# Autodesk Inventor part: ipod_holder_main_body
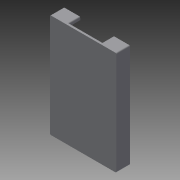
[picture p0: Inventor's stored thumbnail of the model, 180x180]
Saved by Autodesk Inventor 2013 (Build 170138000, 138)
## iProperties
Created: 2013-05
Part Number: ipod_holder_main_body
Material: Generic
Document SubType Name: Modeling
Designer: claudiu
Density: 1 g/cm^3
Author: claudiu
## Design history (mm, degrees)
sketch "Sketch1"
  geometry: L1 (-6.994, -4.785)-(59.006, -4.785); L2 (59.006, -4.785)-(59.006, 98.215); L3 (-6.994, -4.785)-(-6.994, 98.215); L4 (-6.994, 98.215)-(59.006, 98.215); 1 further point
  constraints: 8 end point, 1 horizontal, 1 parallel, 1 perpendicular
  dimensions: "d5" = 103 distance of L3.end L1.start; "d7" = 66 distance of L3.end L2.end
extrude "Extrusion1" new body sketch "Sketch1" distance "d3" = 2; taper "d4" = 0 deg
sketch "Sketch2"
  geometry: L1 (6.994, -98.215)-(6.994, 4.785) reference; L2 (-59.006, 4.785)-(-57.506, 4.785); L3 (-57.506, 4.785)-(-57.506, -95.215); L4 (-57.506, -95.215)-(5.494, -95.215); L5 (5.494, -95.215)-(5.494, 4.785); L6 (-59.006, 4.785)-(-59.006, -98.215) reference; L7 (-59.006, -98.215)-(6.994, -98.215) reference; L8 (6.994, 4.785)-(5.494, 4.785); 1 further point
  constraints: 10 end point, 1 parallel
extrude "Extrusion2" join sketch "Sketch2" distance "d12" = 11.5; taper "d13" = 0 deg
sketch "Sketch6"
  geometry: L1 (5.494, -95.215)-(-57.506, -95.215) reference; L2 (-9.506, -98.215)-(-9.506, -95.215); L3 (-42.506, -98.215)-(-42.506, -95.215); L4 (-9.506, -95.215)-(-42.506, -95.215); L5 (-9.506, -98.215)-(-42.506, -98.215); L6 (-9.506, -95.215)-(-9.506, -98.215); L7 (-9.506, -98.215)-(-42.506, -98.215); L8 (-42.506, -98.215)-(-42.506, -95.215); 1 further point
  constraints: 14 end point, 4 perpendicular, 2 collinear, 2 point on line
extrude "Extrusion6" cut sketch "Sketch6" stored distance "d26" = 10; taper "d27" = 0 deg
fillet "Fillet1" dims "d28" = 1
body "Solid1"
